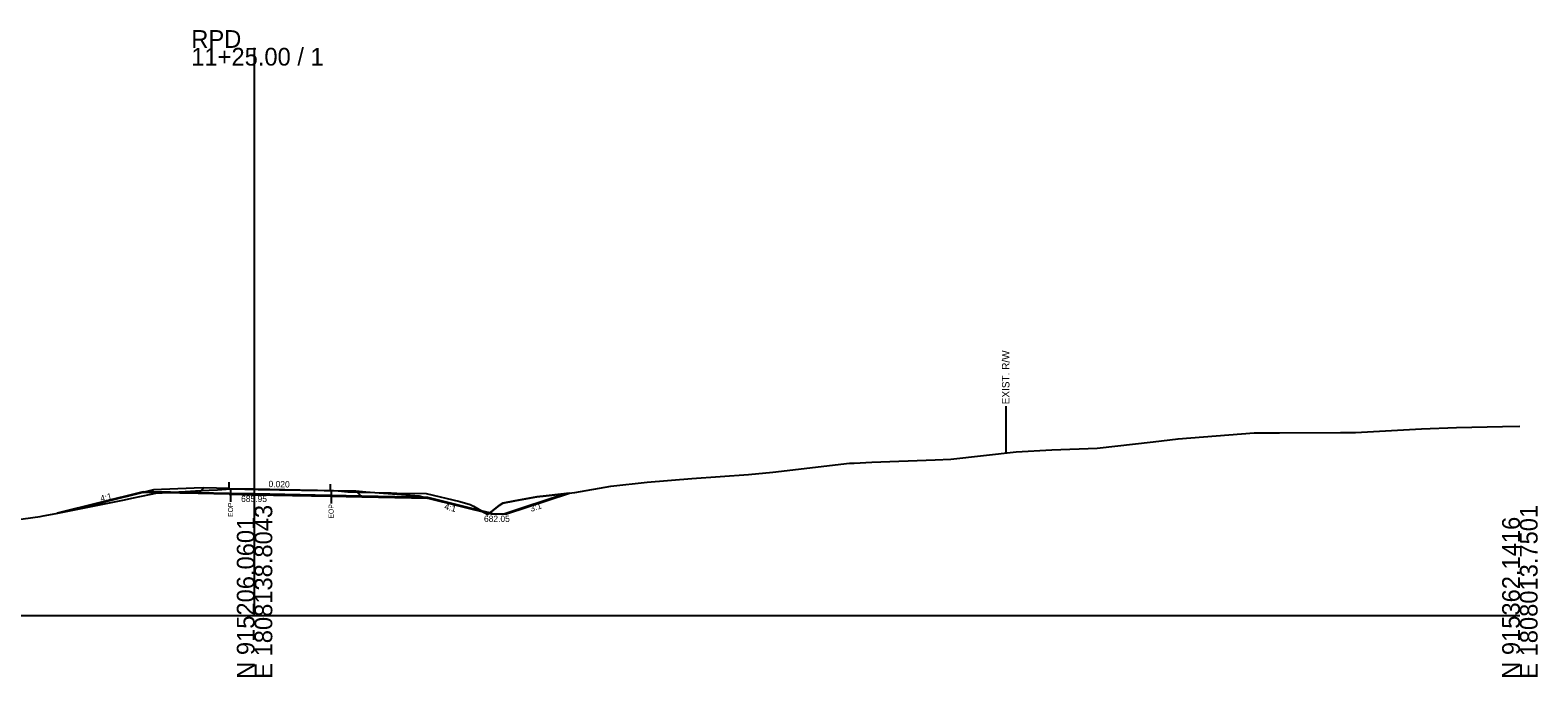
# Model space of a CAD drawing. Extents: x -26 to 403, y -10 to 8517.
# Drawn here: x 164.5 to 402.8, y 2490.3 to 2592.5 of the extents above; entities that cross this region are included whole.
import ezdxf

# ---------------------------------------------------------------- set-up
doc = ezdxf.new("R2010")
doc.units = 0
for name, color, linetype in [('Exist Cross Section Cell', 7, 'Continuous'), ('Exist XS Center Line Elevation Label', 7, 'Continuous'), ('Exist XS Ground Line', 7, 'Continuous'), ('Old_Level_10', 7, 'Continuous'), ('Prop XS Ditch Slope Text', 7, 'Continuous'), ('Prop XS Ditch Standard Text', 7, 'Continuous'), ('Prop XS Earthwork Shape', 7, 'Continuous'), ('Prop XS EOT Tick Mark', 7, 'Continuous'), ('Prop XS Finish Grade', 7, 'Continuous'), ('Prop XS Finish Grade Earthwork', 7, 'Continuous'), ('Prop XS Finish Grade Paved Shoulder', 7, 'Continuous'), ('Prop XS Finish Grade Pavement', 7, 'Continuous'), ('Prop XS Hydro Fill Slope Data', 7, 'Continuous'), ('Prop XS Pvmt Edge Slope', 7, 'Continuous'), ('Prop XS SE Text', 7, 'Continuous'), ('Prop XS Side Slope Text', 7, 'Continuous'), ('Prop XS Subgrade Earthwork', 7, 'Continuous')]:
    doc.layers.add(name, color=color, linetype=linetype)

msp = doc.modelspace()

# ---------------------------------------------------------------- linework, layer by layer
at = {"layer": 'Exist Cross Section Cell'}
for p, q in [((200, 2500), (200, 2589.72)), ((0, 2500), (200, 2500)), ((200, 2500), (400, 2500))]:
    msp.add_line(p, q, dxfattribs=at)
at = {"layer": 'Exist XS Ground Line'}
msp.add_lwpolyline([(153.79, 2513.99), (166.1, 2515.65), (166.61, 2515.73), (168.64, 2516.14), (179.42, 2518.27), (180.61, 2518.55), (183.66, 2519.19), (184.39, 2519.34), (187.42, 2519.52), (188.05, 2519.56), (189.02, 2519.62), (190.65, 2519.71), (192.84, 2519.83), (194.16, 2519.86), (195.52, 2519.95), (196.21, 2520.02), (196.59, 2520.01), (197.35, 2520), (198.47, 2519.98), (200, 2519.95), (200.57, 2519.94), (202.03, 2519.92), (203.96, 2519.89), (206.97, 2519.84), (207.4, 2519.83), (209.97, 2519.79), (211, 2519.77), (212.09, 2519.76), (212.46, 2519.74), (213.21, 2519.7), (214.72, 2519.57), (215.56, 2519.53), (216.29, 2519.5), (217.88, 2519.47), (220.18, 2519.41), (221.57, 2519.38), (222.51, 2519.36), (227.12, 2519.28), (232.45, 2518.03), (234.07, 2517.53), (234.63, 2517.26), (236.85, 2515.94), (238.65, 2517.39), (239.22, 2517.74), (241.16, 2518.11), (244.64, 2518.75), (246.07, 2518.92), (250.6, 2519.45), (256.3, 2520.42), (262.06, 2521.08), (269.12, 2521.64), (278.05, 2522.3), (281.93, 2522.66), (294.05, 2524.08), (294.75, 2524.1), (297.56, 2524.22), (307.56, 2524.62), (310.04, 2524.72), (320.37, 2525.87), (326.03, 2526.19), (333.19, 2526.44), (342.03, 2527.44), (346, 2527.95), (358.02, 2528.89), (358.81, 2528.89), (362.02, 2528.89), (371.63, 2528.91), (374.01, 2528.92), (384.44, 2529.51), (390, 2529.73), (397.26, 2529.86), (400, 2529.91)], dxfattribs=at)
at = {"layer": 'Old_Level_10'}
for p, q in [((318.73, 2533.09), (318.73, 2525.69)), ((196.21, 2520.02), (196.21, 2517.97)), ((212.09, 2519.76), (212.09, 2517.71))]:
    msp.add_line(p, q, dxfattribs=at)
at = {"layer": 'Prop XS Earthwork Shape'}
for points in [[(186.71, 2519.48), (182.38, 2519.57), (168.81, 2516.17), (179.42, 2518.27), (180.61, 2518.55), (183.66, 2519.19), (184.39, 2519.34)], [(186.71, 2519.48), (187.42, 2519.52), (188.05, 2519.56), (189.02, 2519.62), (190.65, 2519.71), (192.84, 2519.83), (194.16, 2519.86), (195.52, 2519.95), (196.21, 2520.02), (196.59, 2520.01), (197.35, 2520), (198.47, 2519.98), (200, 2519.95), (200.57, 2519.94), (202.03, 2519.92), (203.96, 2519.89), (206.97, 2519.84), (207.4, 2519.83), (209.97, 2519.79), (211, 2519.77), (212.09, 2519.76), (212.46, 2519.74), (213.21, 2519.7), (214.72, 2519.57), (215.56, 2519.53), (216.29, 2519.5), (217.88, 2519.47), (220.18, 2519.41), (221.57, 2519.38), (222.51, 2519.36), (227.12, 2519.28), (232.45, 2518.03), (234.07, 2517.53), (234.63, 2517.26), (235.81, 2516.56), (227.38, 2518.67), (216.94, 2518.87), (211.98, 2518.97), (199.98, 2519.21), (195.98, 2519.29), (191.1, 2519.39)], [(237.19, 2516.21), (237.84, 2516.05), (239.84, 2516.05), (249.77, 2519.36), (246.07, 2518.92), (244.64, 2518.75), (241.16, 2518.11), (239.22, 2517.74), (238.65, 2517.39)], [(235.81, 2516.56), (236.85, 2515.94), (237.19, 2516.21)]]:
    msp.add_lwpolyline(points, close=True, dxfattribs=at)
at = {"layer": 'Prop XS EOT Tick Mark'}
for p, q in [((196, 2520.1), (196, 2521.1)), ((212, 2519.78), (212, 2520.78))]:
    msp.add_line(p, q, dxfattribs=at)
at = {"layer": 'Prop XS Finish Grade'}
for p, q in [((182.38, 2519.46), (184, 2519.86)), ((190.43, 2520.12), (184, 2519.86)), ((184, 2519.86), (184, 2519.86)), ((192, 2520.18), (190.43, 2520.12)), ((216, 2519.7), (217.57, 2519.57)), ((217.57, 2519.57), (226, 2518.9)), ((226, 2518.9), (227.38, 2518.56)), ((227.38, 2518.56), (227.38, 2518.56))]:
    msp.add_line(p, q, dxfattribs=at)
at = {"layer": 'Prop XS Finish Grade Earthwork'}
for p, q in [((182.38, 2519.46), (170.91, 2516.59)), ((239.4, 2516.05), (249.09, 2519.28)), ((227.38, 2518.56), (237.4, 2516.05)), ((237.4, 2516.05), (239.4, 2516.05))]:
    msp.add_line(p, q, dxfattribs=at)
at = {"layer": 'Prop XS Finish Grade Paved Shoulder'}
for p, q in [((196, 2520.1), (192, 2520.18)), ((212, 2519.78), (216, 2519.7))]:
    msp.add_line(p, q, dxfattribs=at)
at = {"layer": 'Prop XS Finish Grade Pavement'}
for p, q in [((196, 2520.1), (200, 2520.02)), ((200, 2520.02), (212, 2519.78))]:
    msp.add_line(p, q, dxfattribs=at)
at = {"layer": 'Prop XS Hydro Fill Slope Data'}
msp.add_line((184, 2519.86), (170.91, 2516.59), dxfattribs=at)
at = {"layer": 'Prop XS Pvmt Edge Slope'}
for p, q in [((192, 2520.18), (191.1, 2519.28)), ((216, 2519.7), (216.94, 2518.76))]:
    msp.add_line(p, q, dxfattribs=at)
at = {"layer": 'Prop XS Subgrade Earthwork'}
for p, q in [((191.1, 2519.28), (182.38, 2519.46)), ((195.98, 2519.18), (191.1, 2519.28)), ((195.98, 2519.18), (199.98, 2519.1)), ((199.98, 2519.1), (211.98, 2518.86)), ((211.98, 2518.86), (216.94, 2518.76)), ((216.94, 2518.76), (227.38, 2518.56))]:
    msp.add_line(p, q, dxfattribs=at)

# ---------------------------------------------------------------- texts
at = {"layer": 'Exist Cross Section Cell'}
for s, p in [('RPD', (190, 2589.72)), ('11+25.00 / 1', (190, 2586.92))]:
    msp.add_text(s, height=2.8, dxfattribs=at).set_placement(p)
for s, p in [('E 1808138.8043', (202.8, 2490)), ('E 1808013.7501', (402.8, 2490)), ('N 915206.0601', (200, 2490)), ('N 915362.1416', (400, 2490))]:
    msp.add_text(s, height=2.8, rotation=90, dxfattribs=at).set_placement(p)
at = {"layer": 'Exist XS Center Line Elevation Label'}
msp.add_text('685.95', height=1, dxfattribs=at).set_placement((197.87, 2517.95))
at = {"layer": 'Old_Level_10'}
for s, height, rotation, p in [('EXIST. R/W', 1.181, 90, (319.32, 2533.39)), ('EOP', 0.787, 90, (196.6, 2515.57)), ('EOP', 0.787, 90, (212.49, 2515.31)), ('3:1', 1, 18.4349, (243.71, 2516.37))]:
    msp.add_text(s, height=height, rotation=rotation, dxfattribs=at).set_placement(p)
at = {"layer": 'Prop XS Ditch Slope Text'}
msp.add_text('4:1', height=1, rotation=345.9638, dxfattribs=at).set_placement((229.93, 2516.8))
at = {"layer": 'Prop XS Ditch Standard Text'}
msp.add_text('682.05', height=1, dxfattribs=at).set_placement((236.26, 2514.79))
at = {"layer": 'Prop XS SE Text'}
msp.add_text('0.020', height=1, rotation=358.8542, dxfattribs=at).set_placement((202.2, 2520.3))
at = {"layer": 'Prop XS Side Slope Text'}
msp.add_text('4:1', height=1, rotation=14.0362, dxfattribs=at).set_placement((175.74, 2517.97))

doc.saveas('drawing.dxf')
